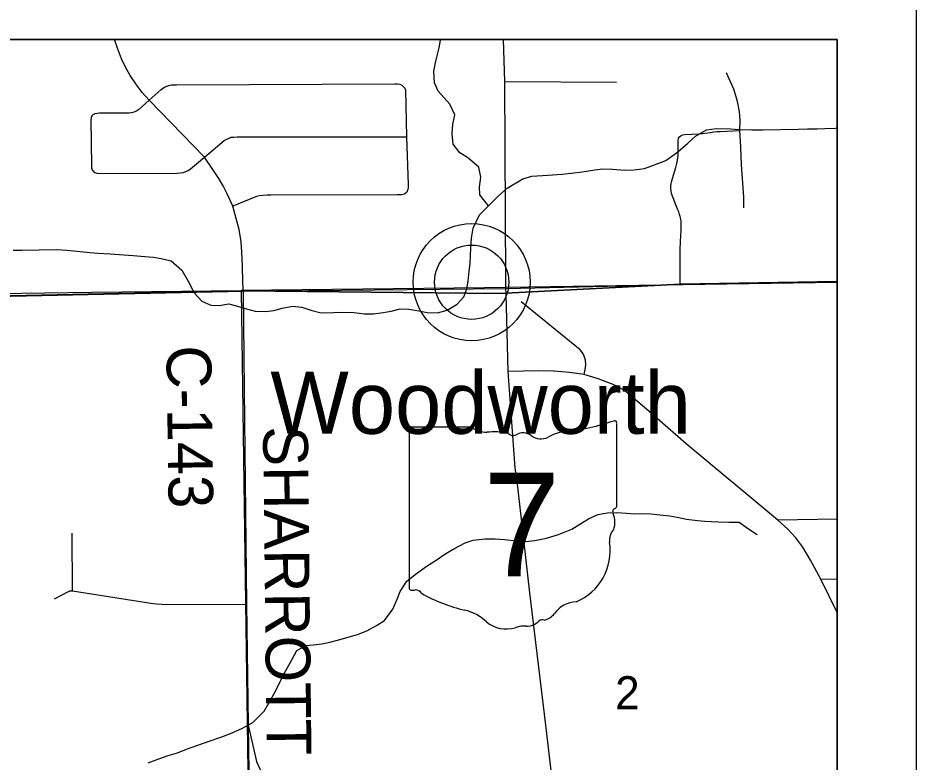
# Model space of a CAD drawing. Extents: x 0 to 36.9, y 0 to 22.
# Drawn here: x 7.859 to 9, y 19.983 to 20.927 of the extents above; entities that cross this region are included whole.
import ezdxf

# ---------------------------------------------------------------- set-up
doc = ezdxf.new("R2010")
doc.units = 0
for name, color, linetype in [('Default', 7, 'Continuous'), ('GM_X_County_Road', 7, 'Continuous'), ('GM_X_County_Road_Text', 7, 'Continuous'), ('GM_X_Minor_River', 7, 'Continuous'), ('GM_X_Rail_Line', 7, 'Continuous'), ('GM_X_Section', 7, 'Continuous'), ('GM_X_Section_Text', 7, 'Continuous'), ('GM_X_State_Location', 7, 'Continuous'), ('GM_X_State_Route', 7, 'Continuous'), ('GM_X_State_Shield', 7, 'Continuous'), ('GM_X_Township_Road', 7, 'Continuous'), ('GM_X_Unincorporated', 7, 'Continuous'), ('GM_X_Unincorporated_Location', 7, 'Continuous'), ('GM_X_Unincorporated_Text', 7, 'Continuous'), ('SH_Cut_Line', 7, 'Continuous'), ('SH_Data', 7, 'Continuous')]:
    doc.layers.add(name, color=color, linetype=linetype)

msp = doc.modelspace()

# ---------------------------------------------------------------- linework, layer by layer
at = {"layer": 'Default'}
msp.add_lwpolyline([(8.9, 19.5814), (8.9, 20.5914), (8.452, 20.5848), (8.1429, 20.5815), (8.157, 19.5752)], close=True, dxfattribs=at)
at = {"layer": 'GM_X_County_Road'}
msp.add_line((8.1453, 20.5805), (8.1447, 20.6101), dxfattribs=at)
for points in [[(8.1447, 20.6101), (8.1447, 20.6121), (8.1439, 20.6303), (8.1427, 20.6432), (8.1402, 20.6586), (8.1366, 20.6729), (8.1323, 20.6884), (8.1251, 20.7042), (8.1199, 20.7144), (8.1145, 20.7237), (8.1067, 20.7351), (8.0961, 20.7505), (8.0262, 20.8228), (8.0169, 20.8328), (8.009, 20.8438), (8.0019, 20.8543), (7.9961, 20.8649), (7.9907, 20.8754), (7.9856, 20.8889), (7.9821, 20.9)], [(8.4791, 20.5838), (8.7006, 20.5888), (8.9, 20.5922)], [(7.7516, 20.5719), (8.1453, 20.5805), (8.4791, 20.5838)], [(8.1453, 20.5805), (8.1466, 20.4558), (8.1498, 20.1833), (8.1528, 19.9385), (8.1544, 19.7311)]]:
    msp.add_lwpolyline(points, dxfattribs=at)
at = {"layer": 'GM_X_Minor_River'}
for points in [[(8.4569, 20.689), (8.4461, 20.7029), (8.4455, 20.7124), (8.4472, 20.7254), (8.4447, 20.7378), (8.4304, 20.7501), (8.4205, 20.756), (8.4123, 20.7672), (8.4109, 20.7801), (8.4118, 20.7927), (8.4143, 20.8045), (8.408, 20.8177), (8.3932, 20.8345), (8.3885, 20.845), (8.3875, 20.8598), (8.3899, 20.8724), (8.3942, 20.8892), (8.3959, 20.8991), (8.396, 20.9)], [(8.345, 20.558), (8.356, 20.5578), (8.3686, 20.5554), (8.3789, 20.5533), (8.3922, 20.5528), (8.4046, 20.5564), (8.417, 20.5639), (8.4256, 20.5735), (8.4296, 20.5834), (8.4313, 20.593), (8.4326, 20.6059), (8.4336, 20.6158), (8.4342, 20.6257), (8.4344, 20.6352), (8.4353, 20.6477), (8.4377, 20.6606), (8.4454, 20.6775), (8.4585, 20.6906), (8.4697, 20.7015), (8.4805, 20.7111), (8.5004, 20.7233), (8.5121, 20.7265), (8.5254, 20.7275), (8.5383, 20.7281), (8.5504, 20.7291), (8.5618, 20.7304), (8.5758, 20.7322), (8.5921, 20.7344), (8.602, 20.7357), (8.6145, 20.7355), (8.6301, 20.7343), (8.6422, 20.7345), (8.6551, 20.7363), (8.6679, 20.7407), (8.6823, 20.7462), (8.6976, 20.7575), (8.71, 20.7684), (8.7201, 20.7773), (8.734, 20.7851), (8.7465, 20.7868), (8.7643, 20.7864), (8.7761, 20.7859), (8.7913, 20.7854), (8.8057, 20.7852), (8.8505, 20.786), (8.8623, 20.7866), (8.8745, 20.7865), (8.8843, 20.787), (8.8976, 20.7876), (8.9, 20.7879)], [(7.8531, 20.6327), (7.8641, 20.6325), (7.9081, 20.6333), (7.9214, 20.6324), (7.9385, 20.6308), (7.9507, 20.6295), (7.961, 20.6286), (7.9766, 20.6277), (7.994, 20.6265), (8.0055, 20.6256), (8.0207, 20.6247), (8.0317, 20.6238), (8.0412, 20.6221), (8.0538, 20.6189), (8.0673, 20.607), (8.0755, 20.5931), (8.083, 20.5784), (8.0927, 20.5679), (8.1045, 20.5628), (8.1148, 20.5623), (8.1273, 20.5644), (8.1384, 20.5615), (8.1479, 20.5583), (8.1605, 20.5551), (8.1742, 20.5546), (8.1844, 20.5559), (8.195, 20.5588), (8.2079, 20.5613), (8.2197, 20.56), (8.2315, 20.5564), (8.2445, 20.5528), (8.26, 20.5535), (8.2703, 20.554), (8.2862, 20.5532), (8.2992, 20.5519), (8.3109, 20.5517), (8.3234, 20.5535), (8.3333, 20.5552), (8.345, 20.558)], [(8.1906, 20.0811), (8.1964, 20.093), (8.2045, 20.1076), (8.2137, 20.1241), (8.225, 20.1307), (8.2345, 20.1313), (8.2455, 20.1326), (8.2553, 20.1347), (8.2651, 20.1375), (8.2908, 20.1448), (8.3025, 20.1492), (8.3149, 20.1559), (8.3247, 20.1625), (8.3355, 20.1767), (8.3409, 20.1894), (8.3449, 20.1993), (8.3534, 20.2124), (8.3654, 20.2221), (8.3789, 20.2318), (8.3905, 20.2392), (8.4029, 20.2474), (8.4131, 20.2533), (8.4274, 20.2611), (8.4376, 20.2643), (8.4527, 20.2661), (8.4653, 20.266), (8.4774, 20.2654), (8.493, 20.2634), (8.5044, 20.2625), (8.5158, 20.2638), (8.5305, 20.2671), (8.546, 20.2716), (8.563, 20.2783), (8.5728, 20.2846), (8.584, 20.2916), (8.5957, 20.2971), (8.6082, 20.2989), (8.62, 20.2995), (8.6321, 20.2985), (8.642, 20.298), (8.6515, 20.2981), (8.6637, 20.2976), (8.6747, 20.2966), (8.6873, 20.2954), (8.6968, 20.2936), (8.7086, 20.2912), (8.7223, 20.2895), (8.7318, 20.2886), (8.7485, 20.2877), (8.7622, 20.2872), (8.7755, 20.2874), (8.787, 20.2789), (8.7982, 20.2715)], [(8.0249, 19.9817), (8.0381, 19.9869), (8.0502, 19.9909), (8.0619, 19.9945), (8.0736, 19.9989), (8.089, 20.0045), (8.1022, 20.0093), (8.117, 20.0141), (8.1294, 20.0189), (8.1437, 20.0252), (8.1576, 20.0327), (8.1722, 20.0474), (8.1785, 20.0585), (8.1843, 20.0689), (8.1906, 20.0811)], [(8.1519, 20.0296), (8.1623, 19.9834), (8.169, 19.9684), (8.182, 19.9633), (8.1942, 19.965), (8.2064, 19.9599), (8.2164, 19.9506), (8.2288, 19.9417), (8.2398, 19.9374), (8.2582, 19.9313), (8.2719, 19.9304), (8.2904, 19.9322), (8.3018, 19.9339), (8.3163, 19.9323), (8.3273, 19.931), (8.3402, 19.9289), (8.3539, 19.9303), (8.3667, 19.9332), (8.3811, 19.935), (8.3933, 19.934), (8.4038, 19.9213), (8.415, 19.9117), (8.4249, 19.9115), (8.4488, 19.9102)]]:
    msp.add_lwpolyline(points, dxfattribs=at)
at = {"layer": 'GM_X_Rail_Line'}
msp.add_lwpolyline([(8.9, 20.5927), (8.9, 20.9), (5.9205, 20.9), (5.9236, 20.5446), (6.1727, 20.5478), (7.1468, 20.5633), (7.1656, 20.5637), (7.4889, 20.5693), (7.7514, 20.5725), (8.1451, 20.581), (8.4706, 20.5777), (8.4791, 20.5781), (8.7004, 20.5894)], close=True, dxfattribs=at)
msp.add_lwpolyline([(8.9, 14.5158), (8.9, 20.5927), (8.7004, 20.5894), (8.4791, 20.5781), (8.4706, 20.5777), (8.1451, 20.581), (7.7514, 20.5725), (7.4889, 20.5693), (7.1656, 20.5637), (7.1468, 20.5633), (6.1727, 20.5478), (5.9236, 20.5446), (5.3186, 20.5329), (5.2978, 20.5324), (5.1496, 20.5295), (4.5929, 20.5183), (4.1742, 20.5119), (4.2095, 19.5156), (4.2124, 19.4314), (4.22, 18.531), (4.2174, 18.4382), (4.2214, 17.442), (4.2237, 16.806), (4.2428, 16.065)], dxfattribs=at)
at = {"layer": 'GM_X_Section'}
msp.add_lwpolyline([(8.1429, 20.5815), (8.157, 19.5752), (7.1591, 19.5574), (7.1483, 20.5676), (7.9531, 20.5791)], close=True, dxfattribs=at)
at = {"layer": 'GM_X_State_Route'}
msp.add_line((8.4791, 20.5838), (8.4791, 20.5939), dxfattribs=at)
for points in [[(8.4791, 20.5939), (8.4777, 20.8468), (8.4761, 20.9)], [(8.4932, 20.3393), (8.491, 20.3561), (8.482, 20.4784), (8.4793, 20.5775), (8.4791, 20.5838)], [(8.5396, 20.4791), (8.5209, 20.4794), (8.482, 20.4784)], [(8.6332, 20.4513), (8.6294, 20.4546), (8.6154, 20.4622), (8.5962, 20.4692), (8.5783, 20.4745), (8.5599, 20.4772), (8.5405, 20.4791), (8.5396, 20.4791)], [(8.6711, 20.4187), (8.6575, 20.4305), (8.6332, 20.4513)], [(8.8246, 20.2896), (8.7082, 20.3867), (8.6711, 20.4187)], [(8.6082, 19.3968), (8.6074, 19.4019), (8.5937, 19.4979), (8.5809, 19.5847), (8.5704, 19.6843), (8.5621, 19.7633), (8.5494, 19.8642), (8.5296, 20.0295), (8.5094, 20.1975), (8.4969, 20.3096), (8.4932, 20.3393)], [(8.9, 20.1725), (8.8789, 20.2147), (8.8658, 20.2392), (8.8562, 20.2557), (8.8472, 20.2673), (8.8371, 20.2783), (8.8246, 20.2896)]]:
    msp.add_lwpolyline(points, dxfattribs=at)
at = {"layer": 'GM_X_State_Shield'}
for p, q in [((8.436, 20.4078), (8.3588, 20.4078)), ((8.6199, 20.3081), (8.6199, 20.4127)), ((8.3562, 20.4043), (8.3562, 20.2042)), ((8.6198, 20.3081), (8.6199, 20.3081))]:
    msp.add_line(p, q, dxfattribs=at)
for centre, radius, start, end in [((8.3592, 20.4048), 0.00305, 98.1301, 188.1301), ((8.4544, 20.431), 0.0296, 231.6195, 271.1119), ((8.5259, 20.6806), 0.2796, 275.8445, 288.9065), ((8.6169, 20.4132), 0.00294, 351.8621, 97.738), ((8.4642, 20.2954), 0.1064, 80.4867, 94.9883), ((8.4884, 20.4058), 0.00855, 219.7921, 297.1024), ((8.5009, 20.3827), 0.0178, 54.4667, 119.1411), ((8.5238, 20.4144), 0.0214, 233.8562, 294.8282), ((8.5616, 20.3467), 0.0563, 97.3462, 120.7689), ((8.6192, 20.3004), 0.00454, 107.944, 210.337), ((8.6167, 20.3077), 0.00314, 289.6038, 7.7341), ((8.5903, 20.2871), 0.0273, 340.033, 23.6496), ((8.6304, 20.2643), 0.0198, 136.8065, 186.9296), ((8.5416, 20.2509), 0.0699, 292.3089, 8.9858), ((8.3592, 20.2038), 0.00308, 171.9584, 258.3066), ((8.3597, 20.2243), 0.0235, 267.339, 280.6039), ((8.3645, 20.1927), 0.00848, 29.7484, 93.2717), ((8.4716, 20.3725), 0.2019, 240.4129, 257.1985), ((8.5711, 20.148), 0.0383, 94.4031, 142.5768), ((8.4114, 20.1143), 0.0632, 47.1842, 75.836), ((8.5226, 20.1848), 0.0226, 282.8732, 323.2771), ((8.4797, 20.1917), 0.0401, 230.7004, 286.2918), ((8.5029, 20.1225), 0.0329, 85.6951, 111.2099), ((8.5058, 20.1767), 0.0214, 268.777, 315.5493), ((8.5251, 20.1573), 0.00601, 65.7517, 132.6484)]:
    msp.add_arc(centre, radius, start, end, dxfattribs=at)
at = {"layer": 'GM_X_Township_Road'}
for p, q in [((8.4777, 20.8468), (8.6196, 20.8457)), ((8.9, 20.2911), (8.8246, 20.2896)), ((7.9288, 20.2), (7.9283, 20.2731)), ((8.8789, 20.2147), (8.9, 20.2151))]:
    msp.add_line(p, q, dxfattribs=at)
for points in [[(8.7811, 20.6862), (8.7814, 20.7004), (8.7784, 20.741), (8.7773, 20.7632), (8.7764, 20.7844), (8.7765, 20.7976), (8.7763, 20.8032), (8.7758, 20.8083), (8.7751, 20.8125), (8.7739, 20.8176), (8.7727, 20.823), (8.7708, 20.8298), (8.7686, 20.8371), (8.7645, 20.8464), (8.7591, 20.8578)], [(8.0262, 20.8228), (8.0413, 20.8367), (8.0445, 20.839), (8.0475, 20.8405), (8.0508, 20.8416), (8.0542, 20.8423), (8.0569, 20.8425), (8.0608, 20.8426), (8.3381, 20.8435), (8.3414, 20.8435), (8.3445, 20.8432), (8.3468, 20.842), (8.3488, 20.8404), (8.3506, 20.8383), (8.3514, 20.8361), (8.353, 20.7766), (8.355, 20.7157), (8.3548, 20.7122), (8.3545, 20.7095), (8.3533, 20.7062), (8.3505, 20.7037), (8.3465, 20.7029), (8.3415, 20.7027), (8.1804, 20.7022), (8.176, 20.7023), (8.1703, 20.7021), (8.1662, 20.7016), (8.1625, 20.7006), (8.1323, 20.6884)], [(8.0262, 20.8228), (8.0126, 20.8108), (8.01, 20.8091), (8.0065, 20.8077), (8.0036, 20.8069), (8.0003, 20.8065), (7.9974, 20.8063), (7.9628, 20.8063), (7.9598, 20.8061), (7.957, 20.8056), (7.9546, 20.8045), (7.9533, 20.803), (7.9522, 20.8008), (7.9517, 20.7981), (7.9526, 20.7398), (7.9528, 20.7369), (7.9535, 20.7347), (7.955, 20.7328), (7.9571, 20.7313), (7.9596, 20.7302), (7.9632, 20.7299), (8.0617, 20.7304), (8.0659, 20.7307), (8.0692, 20.7313), (8.0726, 20.7323), (8.0756, 20.7338), (8.0785, 20.7359), (8.0961, 20.7505)], [(8.7006, 20.5888), (8.7003, 20.6206), (8.7004, 20.6324), (8.7007, 20.6441), (8.7016, 20.6577), (8.7018, 20.6644), (8.7016, 20.6686), (8.7013, 20.6721), (8.7006, 20.6751), (8.6997, 20.678), (8.6986, 20.6811), (8.6972, 20.6844), (8.6895, 20.7046), (8.689, 20.7078), (8.6887, 20.7108), (8.6887, 20.7138), (8.6889, 20.7166), (8.6895, 20.7195), (8.6949, 20.7375), (8.6961, 20.7425), (8.6971, 20.747), (8.6977, 20.7529), (8.6979, 20.7589), (8.6977, 20.7713), (8.6983, 20.7746), (8.6994, 20.7765), (8.7016, 20.7781), (8.7037, 20.7789), (8.7058, 20.7794), (8.7249, 20.7802), (8.7388, 20.7821), (8.743, 20.7826), (8.7473, 20.7831), (8.7511, 20.7833), (8.7764, 20.7844)], [(8.0961, 20.7505), (8.1213, 20.7716), (8.1247, 20.7736), (8.1276, 20.7749), (8.1303, 20.7758), (8.1336, 20.7762), (8.1379, 20.7763), (8.353, 20.7766)], [(8.5783, 20.4745), (8.5797, 20.4812), (8.5807, 20.4868), (8.5803, 20.4928), (8.5778, 20.5004), (8.5736, 20.506), (8.4986, 20.5671)], [(7.9058, 20.19), (7.9235, 20.1994), (7.9248, 20.1999), (7.9261, 20.2001), (7.9274, 20.2001), (7.9288, 20.2), (8.028, 20.1844), (8.0351, 20.1836), (8.0419, 20.183), (8.0479, 20.1827), (8.1498, 20.1833)]]:
    msp.add_lwpolyline(points, dxfattribs=at)
at = {"layer": 'GM_X_Unincorporated'}
for radius in [0.0744, 0.0472]:
    msp.add_circle((8.4356, 20.5919), radius, dxfattribs=at)
at = {"layer": 'GM_X_Unincorporated_Location'}
msp.add_line((8.4356, 20.5919), (8.4356, 20.5919), dxfattribs=at)
at = {"layer": 'SH_Cut_Line'}
msp.add_lwpolyline([(8.9, 14.5158), (8.9, 20.9), (2.1, 20.9), (2.1, 14.4405)], dxfattribs=at)
at = {"layer": 'SH_Data'}
for p, q in [((9, 21), (9, 14)), ((2.1, 20.9), (8.9, 20.9)), ((8.9, 20.9), (8.9, 14.1))]:
    msp.add_line(p, q, dxfattribs=at)

# ---------------------------------------------------------------- texts
at = {"layer": 'GM_X_County_Road_Text'}
for s, rotation, p in [('C-143', 270.8269, (8.0478, 20.5113)), ('SHARROTT', 270.6492, (8.1706, 20.4088))]:
    msp.add_text(s, height=0.05682, rotation=rotation, dxfattribs=at).set_placement(p)
at = {"layer": 'GM_X_Section_Text'}
msp.add_text('2', height=0.0419, rotation=0, dxfattribs=at).set_placement((8.6178, 20.0498))
at = {"layer": 'GM_X_State_Location'}
for s, p in [('s', (8.4851, 20.291)), ('r', (8.485, 20.291))]:
    msp.add_text(s, height=0.000189, dxfattribs=at).set_placement(p)
msp.add_text('7', height=0.000189, rotation=0, dxfattribs=at).set_placement((8.4565, 20.2772))
at = {"layer": 'GM_X_State_Shield'}
msp.add_text('7', height=0.1318, dxfattribs=at).set_placement((8.4502, 20.2183))
at = {"layer": 'GM_X_Unincorporated_Text'}
msp.add_text('Woodworth', height=0.07898, rotation=0, dxfattribs=at).set_placement((8.1799, 20.3994))

doc.saveas('drawing.dxf')
